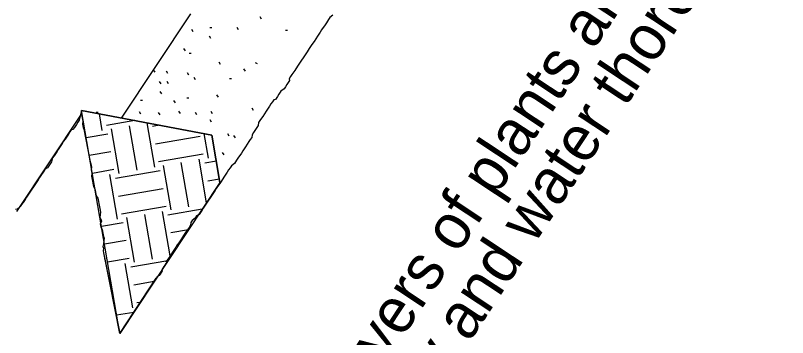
# Model space of a CAD drawing. Extents: x 561231 to 564240, y 590260 to 602519.
# Drawn here: x 563652.7 to 563716.2, y 590442.9 to 590469.5 of the extents above; entities that cross this region are included whole.
import ezdxf

# ---------------------------------------------------------------- set-up
doc = ezdxf.new("R2010")
doc.units = 0
doc.layers.add('Old_Level_1', color=7, linetype='Continuous')

msp = doc.modelspace()

# ---------------------------------------------------------------- linework, layer by layer
at = {"layer": 'Old_Level_1'}
for p, q in [((563661.409, 590461.001), (563667.107, 590469.591)), ((563672.922, 590469.143), (563672.802, 590469.333)), ((563667.302, 590468.116), (563667.181, 590468.307)), ((563668.674, 590468.471), (563668.839, 590468.472)), ((563671.024, 590468.263), (563670.903, 590468.454)), ((563674.878, 590468.246), (563675.044, 590468.247)), ((563668.746, 590467.561), (563668.624, 590467.752)), ((563666.655, 590466.533), (563666.533, 590466.724)), ((563666.969, 590466.35), (563667.134, 590466.35)), ((563669.542, 590465.422), (563669.421, 590465.613)), ((563672.384, 590465.586), (563672.568, 590465.491)), ((563664.16, 590464.772), (563664.039, 590464.962)), ((563671.591, 590464.868), (563671.47, 590465.059)), ((563665.217, 590464.669), (563665.095, 590464.86)), ((563666.939, 590464.533), (563666.817, 590464.724)), ((563667.498, 590464.162), (563667.377, 590464.353)), ((563664.661, 590463.831), (563664.539, 590464.021)), ((563665.266, 590463.832), (563665.144, 590464.023)), ((563670.277, 590464.258), (563670.443, 590464.258)), ((563664.709, 590462.993), (563664.588, 590463.185)), ((563662.964, 590462.484), (563663.13, 590462.484)), ((563665.828, 590462.251), (563665.707, 590462.442)), ((563666.779, 590462.669), (563666.945, 590462.668)), ((563669.364, 590462.724), (563669.242, 590462.915)), ((563672.26, 590461.628), (563672.139, 590461.819)), ((563658.142, 590461.411), (563652.765, 590453.306)), ((563661.257, 590443.272), (563658.119, 590461.618)), ((563658.119, 590461.618), (563668.84, 590459.608)), ((563668.84, 590459.608), (563658.119, 590461.618)), ((563659.312, 590461.493), (563659.477, 590461.493)), ((563659.821, 590459.988), (563659.588, 590461.342)), ((563662.992, 590461.315), (563662.871, 590461.506)), ((563664.574, 590461.272), (563664.453, 590461.462)), ((563666.249, 590461.368), (563666.127, 590461.559)), ((563667.599, 590461.278), (563667.477, 590461.469)), ((563668.888, 590461.36), (563668.767, 590461.55)), ((563662.488, 590460.799), (563660.156, 590460.397)), ((563664.146, 590456.958), (563663.518, 590460.605)), ((563668.81, 590460.675), (563668.689, 590460.866)), ((563661.213, 590456.453), (563660.581, 590460.12)), ((563662.679, 590456.706), (563662.048, 590460.372)), ((563664.513, 590460.419), (563663.944, 590460.321)), ((563660.278, 590459.69), (563658.501, 590459.384)), ((563667.864, 590459.486), (563664.197, 590458.855)), ((563668.546, 590457.716), (563668.199, 590459.728)), ((563668.84, 590459.608), (563669.498, 590455.696)), ((563669.498, 590455.696), (563668.84, 590459.608)), ((563670.256, 590459.515), (563670.134, 590459.706)), ((563670.768, 590459.377), (563670.647, 590459.568)), ((563660.53, 590458.223), (563658.752, 590457.916)), ((563668.116, 590458.02), (563664.449, 590457.388)), ((563669.841, 590457.979), (563669.72, 590458.17)), ((563666.946, 590453.691), (563666.315, 590457.358)), ((563668.397, 590454.036), (563667.781, 590457.611)), ((563669.203, 590457.452), (563668.242, 590457.286)), ((563660.783, 590456.757), (563659.003, 590456.45)), ((563664.576, 590456.655), (563660.91, 590456.023)), ((563665.479, 590453.439), (563664.848, 590457.105)), ((563661.08, 590452.681), (563660.448, 590456.348)), ((563669.498, 590455.696), (563661.257, 590443.272)), ((563669.449, 590455.984), (563668.495, 590455.82)), ((563664.828, 590455.188), (563661.162, 590454.557)), ((563665.081, 590453.722), (563661.414, 590453.09)), ((563668.043, 590453.503), (563665.203, 590453.014)), ((563663.938, 590449.398), (563663.306, 590453.065)), ((563665.405, 590449.651), (563664.773, 590453.317)), ((563661.536, 590452.382), (563659.751, 590452.075)), ((563662.472, 590449.146), (563661.84, 590452.812)), ((563666.913, 590451.798), (563665.456, 590451.547)), ((563661.789, 590450.916), (563660.002, 590450.608)), ((563665.782, 590450.093), (563665.708, 590450.081)), ((563662.042, 590449.449), (563660.253, 590449.141)), ((563662.338, 590445.374), (563661.707, 590449.041)), ((563665.216, 590449.241), (563662.168, 590448.716)), ((563664.086, 590447.536), (563662.421, 590447.249)), ((563662.955, 590445.831), (563662.673, 590445.783)), ((563662.409, 590445.008), (563661.002, 590444.766)), ((563661.278, 590443.304), (563661.252, 590443.299))]:
    msp.add_line(p, q, dxfattribs=at)
for points in [[(563678.792, 590469.481), (563678.536, 590469.282), (563678.423, 590469.111), (563678.253, 590468.855), (563678.14, 590468.684), (563677.856, 590468.257), (563677.743, 590468.087), (563677.63, 590467.916), (563677.517, 590467.745), (563677.234, 590467.318), (563677.064, 590467.062), (563676.837, 590466.72), (563676.667, 590466.464), (563676.498, 590466.208), (563676.327, 590465.952), (563676.214, 590465.781), (563676.101, 590465.61), (563675.874, 590465.269), (563675.648, 590464.927), (563675.421, 590464.586), (563675.308, 590464.415), (563675.195, 590464.244), (563675.224, 590464.102), (563675.111, 590463.932), (563674.997, 590463.761), (563674.884, 590463.589), (563674.771, 590463.419), (563674.515, 590463.22), (563674.345, 590462.964), (563674.232, 590462.793), (563674.062, 590462.537), (563673.92, 590462.508), (563673.806, 590462.337), (563673.693, 590462.166), (563673.58, 590461.996), (563673.467, 590461.825), (563673.297, 590461.569), (563673.013, 590461.142), (563672.844, 590460.886), (563672.674, 590460.63), (563672.646, 590460.402), (563672.476, 590460.146), (563672.362, 590459.975), (563672.249, 590459.805), (563672.136, 590459.634), (563672.109, 590459.406), (563671.995, 590459.236), (563671.882, 590459.064), (563671.599, 590458.638), (563671.485, 590458.467), (563671.372, 590458.296), (563671.259, 590458.125)], [(563658.119, 590461.618), (563657.919, 590460.827), (563657.805, 590460.656), (563657.692, 590460.486), (563657.522, 590460.229), (563657.409, 590460.058), (563657.267, 590460.03), (563657.154, 590459.859), (563657.04, 590459.688), (563656.87, 590459.432), (563656.757, 590459.261), (563656.644, 590459.091), (563656.53, 590458.92), (563656.417, 590458.749), (563656.304, 590458.578), (563656.19, 590458.407), (563656.077, 590458.237), (563655.964, 590458.066), (563655.851, 590457.896), (563655.737, 590457.725), (563655.653, 590457.412), (563655.54, 590457.241), (563655.426, 590457.07), (563655.313, 590456.899), (563655.115, 590456.785), (563655.001, 590456.614), (563654.888, 590456.444), (563654.775, 590456.273), (563654.661, 590456.102), (563654.548, 590455.932), (563654.322, 590455.59), (563654.151, 590455.334), (563654.038, 590455.163), (563653.925, 590454.992), (563653.812, 590454.821), (563653.698, 590454.65), (563653.585, 590454.48), (563653.472, 590454.309), (563653.302, 590454.053), (563653.189, 590453.882), (563653.076, 590453.712), (563652.82, 590453.512), (563652.678, 590453.484), (563652.678, 590453.484)], [(563658.119, 590461.618), (563658.145, 590461.169), (563658.173, 590461.026), (563658.202, 590460.884), (563658.231, 590460.742), (563658.203, 590460.515), (563658.232, 590460.373), (563658.261, 590460.231), (563658.29, 590460.089), (563658.319, 590459.947), (563658.347, 590459.805), (563658.376, 590459.662), (563658.405, 590459.521), (563658.434, 590459.378), (563658.462, 590459.236), (563658.491, 590459.094), (563658.52, 590458.952), (563658.549, 590458.81), (563658.578, 590458.668), (563658.607, 590458.526), (563658.636, 590458.384), (563658.664, 590458.242), (563658.693, 590458.1), (563658.722, 590457.958), (563658.75, 590457.816), (563658.78, 590457.674), (563658.808, 590457.532), (563658.837, 590457.39), (563658.866, 590457.247), (563658.895, 590457.105), (563658.923, 590456.964), (563658.895, 590456.736), (563658.924, 590456.594), (563658.953, 590456.452), (563658.925, 590456.224), (563658.954, 590456.082), (563658.983, 590455.941), (563659.012, 590455.798), (563659.041, 590455.656), (563659.069, 590455.514), (563659.098, 590455.372), (563659.212, 590455.174), (563659.241, 590455.032), (563659.27, 590454.89), (563659.298, 590454.747), (563659.328, 590454.606), (563659.442, 590454.407), (563659.47, 590454.265), (563659.499, 590454.122), (563659.528, 590453.98), (563659.557, 590453.839), (563659.586, 590453.696), (563659.615, 590453.554), (563659.643, 590453.412), (563659.672, 590453.27), (563659.645, 590453.043), (563659.617, 590452.815), (563659.731, 590452.617), (563659.759, 590452.475), (563659.646, 590452.304), (563659.675, 590452.162), (563659.704, 590452.02), (563659.818, 590451.821), (563659.847, 590451.679), (563659.876, 590451.537), (563659.904, 590451.395), (563659.933, 590451.253), (563659.962, 590451.111), (563659.934, 590450.883), (563659.907, 590450.656), (563659.878, 590450.428), (563659.907, 590450.287), (563659.88, 590450.059), (563659.908, 590449.917), (563659.937, 590449.775), (563659.966, 590449.633), (563659.995, 590449.491), (563660.013, 590449.399)], [(563671.259, 590458.125), (563670.976, 590457.698), (563670.862, 590457.528), (563670.693, 590457.272), (563670.437, 590457.072), (563670.324, 590456.901), (563670.211, 590456.731), (563670.097, 590456.56), (563669.984, 590456.389), (563669.814, 590456.133), (563669.588, 590455.792), (563669.474, 590455.62), (563669.304, 590455.365), (563669.191, 590455.194), (563669.078, 590455.023), (563668.965, 590454.852), (563668.851, 590454.681), (563668.682, 590454.426), (563668.568, 590454.255), (563668.455, 590454.083), (563668.341, 590453.913), (563668.228, 590453.742), (563668.115, 590453.572), (563668.002, 590453.401), (563667.888, 590453.23), (563667.775, 590453.059), (563667.577, 590452.945), (563667.463, 590452.775), (563667.208, 590452.575), (563667.094, 590452.404), (563667.067, 590452.177), (563666.954, 590452.006), (563666.727, 590451.664), (563666.613, 590451.493), (563666.5, 590451.323), (563666.33, 590451.067), (563666.217, 590450.896), (563666.104, 590450.725), (563665.991, 590450.555), (563665.877, 590450.384), (563665.764, 590450.213), (563665.651, 590450.042), (563665.311, 590449.53), (563665.198, 590449.359), (563665.084, 590449.188), (563665.047, 590449.132)], [(563659.995, 590449.491), (563661.257, 590443.272), (563661.257, 590443.272), (563660.025, 590449.512)], [(563665.311, 590449.53), (563665.208, 590449.395), (563665.123, 590449.267), (563665.145, 590449.16), (563665.06, 590449.032), (563664.975, 590448.904), (563664.89, 590448.776), (563664.805, 590448.648), (563664.72, 590448.52), (563664.741, 590448.413), (563664.656, 590448.285), (563664.572, 590448.157), (563664.487, 590448.029), (563664.338, 590447.943), (563664.252, 590447.815), (563661.257, 590443.272), (563661.257, 590443.272), (563664.252, 590447.815)]]:
    msp.add_lwpolyline(points, dxfattribs=at)

# ---------------------------------------------------------------- texts
for s, p in [('6. Repeat layers of plants and sawdust ', (563668.262, 590418.39)), (' as necessary and water thoroughly.', (563672.248, 590415.745))]:
    msp.add_text(s, height=3.72047, rotation=56.44242, dxfattribs=at).set_placement(p)

doc.saveas('drawing.dxf')
